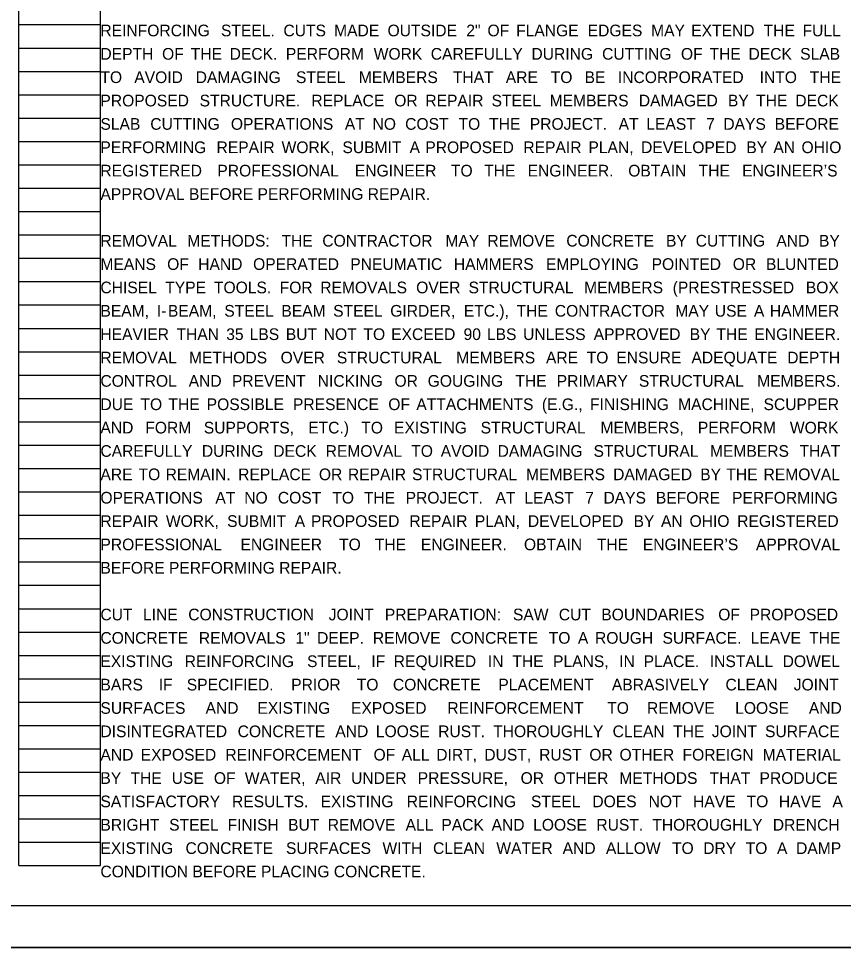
# Model space of a CAD drawing. Extents: x 0 to 34, y 0 to 22.
# Drawn here: x 11.31 to 21.2, y 0 to 11.13 of the extents above; entities that cross this region are included whole.
import ezdxf

# ---------------------------------------------------------------- set-up
doc = ezdxf.new("R2010")
doc.units = 0
for name, color, linetype in [('Default', 7, 'Continuous'), ('SC_Scratch1', 7, 'Continuous'), ('SH_Border', 7, 'Continuous'), ('SH_Cut_Line', 7, 'Continuous')]:
    doc.layers.add(name, color=color, linetype=linetype)

msp = doc.modelspace()

# ---------------------------------------------------------------- linework, layer by layer
at = {"layer": 'SC_Scratch1'}
for p, q in [((11.313, 0.98), (11.313, 21.14)), ((12.293, 0.98), (12.293, 21.14)), ((11.313, 11.06), (12.293, 11.06)), ((11.313, 10.78), (12.293, 10.78)), ((11.313, 10.5), (12.293, 10.5)), ((11.313, 10.22), (12.293, 10.22)), ((11.313, 9.94), (12.293, 9.94)), ((11.313, 9.66), (12.293, 9.66)), ((11.313, 9.38), (12.293, 9.38)), ((11.313, 9.1), (12.293, 9.1)), ((11.313, 8.82), (12.293, 8.82)), ((11.313, 8.54), (12.293, 8.54)), ((11.313, 8.26), (12.293, 8.26)), ((11.313, 7.98), (12.293, 7.98)), ((11.313, 7.7), (12.293, 7.7)), ((11.313, 7.42), (12.293, 7.42)), ((11.313, 7.14), (12.293, 7.14)), ((11.313, 6.86), (12.293, 6.86)), ((11.313, 6.58), (12.293, 6.58)), ((11.313, 6.3), (12.293, 6.3)), ((11.313, 6.02), (12.293, 6.02)), ((11.313, 5.74), (12.293, 5.74)), ((11.313, 5.46), (12.293, 5.46)), ((11.313, 5.18), (12.293, 5.18)), ((11.313, 4.9), (12.293, 4.9)), ((11.313, 4.62), (12.293, 4.62)), ((11.313, 4.34), (12.293, 4.34)), ((11.313, 4.06), (12.293, 4.06)), ((11.313, 3.78), (12.293, 3.78)), ((11.313, 3.5), (12.293, 3.5)), ((11.313, 3.22), (12.293, 3.22)), ((11.313, 2.94), (12.293, 2.94)), ((11.313, 2.66), (12.293, 2.66)), ((11.313, 2.38), (12.293, 2.38)), ((11.313, 2.1), (12.293, 2.1)), ((11.313, 1.82), (12.293, 1.82)), ((11.313, 1.54), (12.293, 1.54)), ((11.313, 1.26), (12.293, 1.26)), ((11.313, 0.98), (12.293, 0.98))]:
    msp.add_line(p, q, dxfattribs=at)
msp.add_lwpolyline([(0, 22), (34, 22), (34, 0), (0, 0)], close=True, dxfattribs=at)
at = {"layer": 'SH_Border'}
msp.add_lwpolyline([(1.5, 21.5), (33.5, 21.5), (33.5, 0.5), (1.5, 0.5)], close=True, dxfattribs=at)
at = {"layer": 'SH_Cut_Line'}
msp.add_lwpolyline([(0, 0), (34, 0), (34, 22), (0, 22)], close=True, dxfattribs=at)

# ---------------------------------------------------------------- texts
at = {"layer": 'Default'}
for s, p in [('REINFORCING ', (12.293, 10.92)), ('STEEL. ', (13.738, 10.92)), ('CUTS ', (14.487, 10.92)), ('MADE ', (15.094, 10.92)), ('OUTSIDE ', (15.735, 10.92)), ('2" ', (16.679, 10.92)), ('OF ', (16.933, 10.92)), ('FLANGE ', (17.276, 10.92)), ('EDGES ', (18.134, 10.92)), ('MAY ', (18.894, 10.92)), ('EXTEND ', (19.375, 10.92)), ('THE ', (20.243, 10.92)), ('FULL ', (20.71, 10.92)), ('DEPTH ', (12.293, 10.64)), ('OF ', (13.032, 10.64)), ('THE ', (13.376, 10.64)), ('DECK. ', (13.842, 10.64)), ('PERFORM ', (14.516, 10.64)), ('WORK ', (15.569, 10.64)), ('CAREFULLY ', (16.253, 10.64)), ('DURING ', (17.46, 10.64)), ('CUTTING ', (18.307, 10.64)), ('OF ', (19.252, 10.64)), ('THE ', (19.595, 10.64)), ('DECK ', (20.062, 10.64)), ('SLAB ', (20.681, 10.64)), ('TO ', (12.293, 10.36)), ('AVOID ', (12.699, 10.36)), ('DAMAGING ', (13.435, 10.36)), ('STEEL ', (14.637, 10.36)), ('MEMBERS ', (15.391, 10.36)), ('THAT ', (16.518, 10.36)), ('ARE ', (17.152, 10.36)), ('TO ', (17.691, 10.36)), ('BE ', (18.097, 10.36)), ('INCORPORATED ', (18.496, 10.36)), ('INTO ', (20.195, 10.36)), ('THE ', (20.796, 10.36)), ('PROPOSED ', (12.293, 10.08)), ('STRUCTURE. ', (13.482, 10.08)), ('REPLACE ', (14.822, 10.08)), ('OR ', (15.815, 10.08)), ('REPAIR ', (16.188, 10.08)), ('STEEL ', (16.982, 10.08)), ('MEMBERS ', (17.678, 10.08)), ('DAMAGED ', (18.747, 10.08)), ('BY ', (19.815, 10.08)), ('THE ', (20.153, 10.08)), ('DECK ', (20.623, 10.08)), ('SLAB ', (12.293, 9.8)), ('CUTTING ', (12.891, 9.8)), ('OPERATIONS ', (13.857, 9.8)), ('AT ', (15.223, 9.8)), ('NO ', (15.555, 9.8)), ('COST ', (15.946, 9.8)), ('TO ', (16.586, 9.8)), ('THE ', (16.952, 9.8)), ('PROJECT. ', (17.44, 9.8)), ('AT ', (18.505, 9.8)), ('LEAST ', (18.837, 9.8)), ('7 ', (19.554, 9.8)), ('DAYS ', (19.76, 9.8)), ('BEFORE ', (20.376, 9.8)), ('PERFORMING ', (12.293, 9.52)), ('REPAIR ', (13.685, 9.52)), ('WORK, ', (14.465, 9.52)), ('SUBMIT ', (15.194, 9.52)), ('A ', (15.999, 9.52)), ('PROPOSED ', (16.188, 9.52)), ('REPAIR ', (17.363, 9.52)), ('PLAN, ', (18.143, 9.52)), ('DEVELOPED ', (18.774, 9.52)), ('BY ', (20.036, 9.52)), ('AN ', (20.36, 9.52)), ('OHIO ', (20.697, 9.52)), ('REGISTERED ', (12.293, 9.24)), ('PROFESSIONAL ', (13.695, 9.24)), ('ENGINEER ', (15.343, 9.24)), ('TO ', (16.495, 9.24)), ('THE ', (16.893, 9.24)), ('ENGINEER. ', (17.414, 9.24)), ('OBTAIN ', (18.62, 9.24)), ('THE ', (19.464, 9.24)), ('ENGINEER’S ', (19.985, 9.24)), ('APPROVAL BEFORE PERFORMING REPAIR. ', (12.293, 8.96)), ('REMOVAL ', (12.293, 8.4)), ('METHODS: ', (13.334, 8.4)), ('THE ', (14.464, 8.4)), ('CONTRACTOR ', (14.953, 8.4)), ('MAY ', (16.428, 8.4)), ('REMOVE ', (16.932, 8.4)), ('CONCRETE ', (17.878, 8.4)), ('BY ', (19.073, 8.4)), ('CUTTING ', (19.429, 8.4)), ('AND ', (20.396, 8.4)), ('BY ', (20.907, 8.4)), ('MEANS ', (12.293, 8.12)), ('OF ', (13.093, 8.12)), ('HAND ', (13.465, 8.12)), ('OPERATED ', (14.123, 8.12)), ('PNEUMATIC ', (15.288, 8.12)), ('HAMMERS ', (16.53, 8.12)), ('EMPLOYING ', (17.633, 8.12)), ('POINTED ', (18.9, 8.12)), ('OR ', (19.873, 8.12)), ('BLUNTED ', (20.271, 8.12)), ('CHISEL ', (12.293, 7.84)), ('TYPE ', (13.07, 7.84)), ('TOOLS. ', (13.654, 7.84)), ('FOR ', (14.442, 7.84)), ('REMOVALS ', (14.928, 7.84)), ('OVER ', (16.078, 7.84)), ('STRUCTURAL ', (16.706, 7.84)), ('MEMBERS ', (18.091, 7.84)), ('(PRESTRESSED ', (19.153, 7.84)), ('BOX ', (20.749, 7.84)), ('BEAM, ', (12.293, 7.56)), ('I-', (12.969, 7.56)), ('BEAM, ', (13.102, 7.56)), ('STEEL ', (13.778, 7.56)), ('BEAM ', (14.462, 7.56)), ('STEEL ', (15.083, 7.56)), ('GIRDER, ', (15.767, 7.56)), ('ETC.), ', (16.649, 7.56)), ('THE ', (17.282, 7.56)), ('CONTRACTOR ', (17.74, 7.56)), ('MAY ', (19.184, 7.56)), ('USE ', (19.658, 7.56)), ('A ', (20.127, 7.56)), ('HAMMER ', (20.318, 7.56)), ('HEAVIER ', (12.293, 7.28)), ('THAN ', (13.205, 7.28)), ('35 ', (13.801, 7.28)), ('LBS ', (14.082, 7.28)), ('BUT ', (14.515, 7.28)), ('NOT ', (14.97, 7.28)), ('TO ', (15.446, 7.28)), ('EXCEED ', (15.778, 7.28)), ('90 ', (16.646, 7.28)), ('LBS ', (16.926, 7.28)), ('UNLESS ', (17.36, 7.28)), ('APPROVED ', (18.206, 7.28)), ('BY ', (19.357, 7.28)), ('THE ', (19.677, 7.28)), ('ENGINEER. ', (20.132, 7.28)), ('REMOVAL ', (12.293, 7)), ('METHODS ', (13.355, 7)), ('OVER ', (14.453, 7)), ('STRUCTURAL ', (15.127, 7)), ('MEMBERS ', (16.558, 7)), ('ARE ', (17.634, 7)), ('TO ', (18.122, 7)), ('ENSURE ', (18.477, 7)), ('ADEQUATE ', (19.378, 7)), ('DEPTH ', (20.526, 7)), ('CONTROL ', (12.293, 6.72)), ('AND ', (13.351, 6.72)), ('PREVENT ', (13.869, 6.72)), ('NICKING ', (14.898, 6.72)), ('OR ', (15.818, 6.72)), ('GOUGING ', (16.216, 6.72)), ('THE ', (17.267, 6.72)), ('PRIMARY ', (17.763, 6.72)), ('STRUCTURAL ', (18.748, 6.72)), ('MEMBERS. ', (20.165, 6.72)), ('DUE ', (12.293, 6.44)), ('TO ', (12.773, 6.44)), ('THE ', (13.108, 6.44)), ('POSSIBLE ', (13.567, 6.44)), ('PRESENCE ', (14.601, 6.44)), ('OF ', (15.744, 6.44)), ('ATTACHMENTS ', (16.08, 6.44)), ('(E.G., ', (17.585, 6.44)), ('FINISHING ', (18.162, 6.44)), ('MACHINE, ', (19.218, 6.44)), ('SCUPPER ', (20.242, 6.44)), ('AND ', (12.293, 6.16)), ('FORM ', (12.831, 6.16)), ('SUPPORTS, ', (13.532, 6.16)), ('ETC.) ', (14.784, 6.16)), ('TO ', (15.42, 6.16)), ('EXISTING ', (15.813, 6.16)), ('STRUCTURAL ', (16.851, 6.16)), ('MEMBERS, ', (18.287, 6.16)), ('PERFORM ', (19.455, 6.16)), ('WORK ', (20.558, 6.16)), ('CAREFULLY ', (12.293, 5.88)), ('DURING ', (13.509, 5.88)), ('DECK ', (14.365, 5.88)), ('REMOVAL ', (14.993, 5.88)), ('TO ', (16.019, 5.88)), ('AVOID ', (16.372, 5.88)), ('DAMAGING ', (17.054, 5.88)), ('STRUCTURAL ', (18.204, 5.88)), ('MEMBERS ', (19.6, 5.88)), ('THAT ', (20.673, 5.88)), ('ARE ', (12.293, 5.6)), ('TO ', (12.75, 5.6)), ('REMAIN. ', (13.074, 5.6)), ('REPLACE ', (13.944, 5.6)), ('OR ', (14.912, 5.6)), ('REPAIR ', (15.26, 5.6)), ('STRUCTURAL ', (16.029, 5.6)), ('MEMBERS ', (17.395, 5.6)), ('DAMAGED ', (18.439, 5.6)), ('BY ', (19.483, 5.6)), ('THE ', (19.796, 5.6)), ('REMOVAL ', (20.242, 5.6)), ('OPERATIONS ', (12.293, 5.32)), ('AT ', (13.671, 5.32)), ('NO ', (14.017, 5.32)), ('COST ', (14.42, 5.32)), ('TO ', (15.073, 5.32)), ('THE ', (15.451, 5.32)), ('PROJECT. ', (15.952, 5.32)), ('AT ', (17.029, 5.32)), ('LEAST ', (17.375, 5.32)), ('7 ', (18.104, 5.32)), ('DAYS ', (18.323, 5.32)), ('BEFORE ', (18.951, 5.32)), ('PERFORMING ', (19.865, 5.32)), ('REPAIR ', (12.293, 5.04)), ('WORK, ', (13.078, 5.04)), ('SUBMIT ', (13.812, 5.04)), ('A ', (14.622, 5.04)), ('PROPOSED ', (14.816, 5.04)), ('REPAIR ', (15.996, 5.04)), ('PLAN, ', (16.781, 5.04)), ('DEVELOPED ', (17.417, 5.04)), ('BY ', (18.684, 5.04)), ('AN ', (19.013, 5.04)), ('OHIO ', (19.355, 5.04)), ('REGISTERED ', (19.926, 5.04)), ('PROFESSIONAL ', (12.293, 4.76)), ('ENGINEER ', (13.972, 4.76)), ('TO ', (15.154, 4.76)), ('THE ', (15.582, 4.76)), ('ENGINEER. ', (16.134, 4.76)), ('OBTAIN ', (17.37, 4.76)), ('THE ', (18.244, 4.76)), ('ENGINEER’S ', (18.795, 4.76)), ('APPROVAL ', (20.151, 4.76)), ('BEFORE PERFORMING REPAIR. ', (12.293, 4.48)), ('CUT ', (12.293, 3.92)), ('LINE ', (12.803, 3.92)), ('CONSTRUCTION ', (13.346, 3.92)), ('JOINT ', (15.029, 3.92)), ('PREPARATION: ', (15.702, 3.92)), ('SAW ', (17.238, 3.92)), ('CUT ', (17.788, 3.92)), ('BOUNDARIES ', (18.297, 3.92)), ('OF ', (19.699, 3.92)), ('PROPOSED ', (20.075, 3.92)), ('CONCRETE ', (12.293, 3.64)), ('REMOVALS ', (13.473, 3.64)), ('1" ', (14.63, 3.64)), ('DEEP. ', (14.89, 3.64)), ('REMOVE ', (15.559, 3.64)), ('CONCRETE ', (16.488, 3.64)), ('TO ', (17.667, 3.64)), ('A ', (18.017, 3.64)), ('ROUGH ', (18.222, 3.64)), ('SURFACE. ', (19.031, 3.64)), ('LEAVE ', (20.087, 3.64)), ('THE ', (20.789, 3.64)), ('EXISTING ', (12.293, 3.36)), ('REINFORCING ', (13.303, 3.36)), ('STEEL, ', (14.77, 3.36)), ('IF ', (15.541, 3.36)), ('REQUIRED ', (15.809, 3.36)), ('IN ', (16.938, 3.36)), ('THE ', (17.231, 3.36)), ('PLANS, ', (17.719, 3.36)), ('IN ', (18.512, 3.36)), ('PLACE. ', (18.805, 3.36)), ('INSTALL ', (19.598, 3.36)), ('DOWEL ', (20.471, 3.36)), ('BARS ', (12.293, 3.08)), ('IF ', (12.992, 3.08)), ('SPECIFIED. ', (13.328, 3.08)), ('PRIOR ', (14.58, 3.08)), ('TO ', (15.366, 3.08)), ('CONCRETE ', (15.799, 3.08)), ('PLACEMENT ', (17.063, 3.08)), ('ABRASIVELY ', (18.424, 3.08)), ('CLEAN ', (19.786, 3.08)), ('JOINT ', (20.604, 3.08)), ('SURFACES ', (12.293, 2.8)), ('AND ', (13.553, 2.8)), ('EXISTING ', (14.175, 2.8)), ('EXPOSED ', (15.297, 2.8)), ('REINFORCEMENT ', (16.452, 2.8)), ('TO ', (18.368, 2.8)), ('REMOVE ', (18.845, 2.8)), ('LOOSE ', (19.902, 2.8)), ('AND ', (20.785, 2.8)), ('DISINTEGRATED ', (12.293, 2.52)), ('CONCRETE ', (13.938, 2.52)), ('AND ', (15.109, 2.52)), ('LOOSE ', (15.595, 2.52)), ('RUST. ', (16.342, 2.52)), ('THOROUGHLY ', (17.001, 2.52)), ('CLEAN ', (18.433, 2.52)), ('THE ', (19.158, 2.52)), ('JOINT ', (19.622, 2.52)), ('SURFACE ', (20.26, 2.52)), ('AND ', (12.293, 2.24)), ('EXPOSED ', (12.776, 2.24)), ('REINFORCEMENT ', (13.791, 2.24)), ('OF ', (15.567, 2.24)), ('ALL ', (15.905, 2.24)), ('DIRT, ', (16.319, 2.24)), ('DUST, ', (16.895, 2.24)), ('RUST ', (17.552, 2.24)), ('OR ', (18.154, 2.24)), ('OTHER ', (18.516, 2.24)), ('FOREIGN ', (19.271, 2.24)), ('MATERIAL ', (20.231, 2.24)), ('BY ', (12.293, 1.96)), ('THE ', (12.654, 1.96)), ('USE ', (13.148, 1.96)), ('OF ', (13.653, 1.96)), ('WATER, ', (14.024, 1.96)), ('AIR ', (14.869, 1.96)), ('UNDER ', (15.298, 1.96)), ('PRESSURE, ', (16.097, 1.96)), ('OR ', (17.33, 1.96)), ('OTHER ', (17.727, 1.96)), ('METHODS ', (18.514, 1.96)), ('THAT ', (19.595, 1.96)), ('PRODUCE ', (20.194, 1.96)), ('SATISFACTORY ', (12.293, 1.68)), ('RESULTS. ', (13.87, 1.68)), ('EXISTING ', (14.932, 1.68)), ('REINFORCING ', (15.965, 1.68)), ('STEEL ', (17.454, 1.68)), ('DOES ', (18.19, 1.68)), ('NOT ', (18.864, 1.68)), ('HAVE ', (19.397, 1.68)), ('TO ', (20.039, 1.68)), ('HAVE ', (20.426, 1.68)), ('A ', (21.068, 1.68)), ('BRIGHT ', (12.293, 1.4)), ('STEEL ', (13.117, 1.4)), ('FINISH ', (13.817, 1.4)), ('BUT ', (14.543, 1.4)), ('REMOVE ', (15.018, 1.4)), ('ALL ', (15.951, 1.4)), ('PACK ', (16.38, 1.4)), ('AND ', (16.982, 1.4)), ('LOOSE ', (17.48, 1.4)), ('RUST. ', (18.238, 1.4)), ('THOROUGHLY ', (18.909, 1.4)), ('DRENCH ', (20.353, 1.4)), ('EXISTING ', (12.293, 1.12)), ('CONCRETE ', (13.313, 1.12)), ('SURFACES ', (14.517, 1.12)), ('WITH ', (15.674, 1.12)), ('CLEAN ', (16.28, 1.12)), ('WATER ', (17.039, 1.12)), ('AND ', (17.834, 1.12)), ('ALLOW ', (18.353, 1.12)), ('TO ', (19.145, 1.12)), ('DRY ', (19.519, 1.12)), ('TO ', (20.028, 1.12)), ('A ', (20.403, 1.12)), ('DAMP ', (20.632, 1.12)), ('CONDITION BEFORE PLACING CONCRETE. ', (12.293, 0.84))]:
    msp.add_text(s, height=0.14, dxfattribs=at).set_placement(p)

doc.saveas('drawing.dxf')
